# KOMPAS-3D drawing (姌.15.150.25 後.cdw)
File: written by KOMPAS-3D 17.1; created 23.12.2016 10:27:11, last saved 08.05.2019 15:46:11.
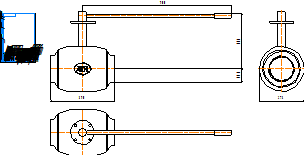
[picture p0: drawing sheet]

Sheet 1: A4, portrait

Title block, sheet 1: name: КШ.15.150.25 сс; material: Внимание! Данный продукт является объектом авторского права ООО «Торговый Дом АДЛ». / Запрещается изменение, копирование, распространение / (в том числе путем копирования на другие сайты и ресурсы в Интернете) / или любое иное использование информации и объектов без предварительного / согласия правообладателя (ООО «Торговый Дом АДЛ»).; sheets: 1; organisation: ООО "Торговый дом АДЛ"; sheet format: A4; stored path: C:\Users\tra\Desktop\2д чертежи\Шаровые краны БИВАЛ\КШ_Бивал_серия_14_15\KOMPAS_2D\КШ.15.150.25 сс.cdw

Views: Вид 1, Проекционный вид 2, Проекционный вид 3
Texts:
  Klimkovich
  ADL
Dimensions and other numbers on the sheet: 390; 900; 336; 79,5; 273; 1:1; 1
